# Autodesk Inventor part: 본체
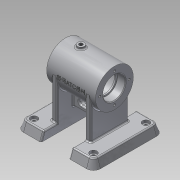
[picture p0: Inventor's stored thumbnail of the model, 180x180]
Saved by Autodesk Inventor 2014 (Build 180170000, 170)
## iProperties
Created: 2016-07
Part Number: 본체
Material: 알루미늄 6061
Document SubType Name: Modeling
Designer: net
Density: 2.71 g/cm^3
Appearance: 알루미늄 - 평지
Mass: 505.561 g
Surface Area: 530.336 cm^2
Volume: 186.554 cm^3
Author: net
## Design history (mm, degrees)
sketch "스케치1"
  geometry: C1 r 27 at (0, 0); 1 further point
  constraints: 1 centre point, 1 coincident
  dimensions: "d0" = 54 diameter of C1
extrude "돌출1" new body sketch "스케치1" stored distance "d1" = 70; taper "d2" = 0 deg
sketch "스케치2"
  geometry: C1 r 22 at (0, 0); 1 further point
  constraints: 1 centre point, 1 coincident
  dimensions: "d3" = 44 diameter of C1
extrude "돌출2" cut sketch "스케치2" stored distance "d4" = 42; taper "d5" = 0 deg
sketch "스케치3"
  geometry: C1 r 27 at (0, 0) reference; C2 r 14 at (0, 0)
  constraints: 1 centre point, 1 coincident
  dimensions: "d6" = 28 diameter of C2
extrude "돌출3" cut sketch "스케치3" stored distance "d7" = 42; taper "d8" = 0 deg
sketch "스케치4"
  geometry: C1 r 14 at (0, 0) reference; C2 r 27 at (0, 0) reference; C3 r 16 at (0, 0)
  constraints: 1 centre point, 1 coincident
  dimensions: "d9" = 32 diameter of C3
extrude "돌출4" cut sketch "스케치4" distance "d10" = 12; taper "d11" = 0 deg
sketch "스케치5"
  geometry: C1 r 14 at (0, 0) reference; C2 r 27 at (0, 0) reference; C3 r 16 at (0, 0)
  constraints: 1 centre point, 1 coincident
  dimensions: "d12" = 32 diameter of C3
extrude "돌출5" cut sketch "스케치5" distance "d13" = 12; taper "d14" = 0 deg
node "작업 평면1"
sketch "스케치6"
  geometry: L1 (-35, 27)-(-35, -27) reference; L2 (35, -27)-(35, 27) reference; L3 (-35, 0)-(35, 0); C1 r 5 at (-13, 0); 1 further point
  constraints: 2 end point, 2 midpoint, 1 centre point, 1 point on line
  dimensions: "d16" = 10 diameter of C1; "d17" = 22 distance of L3.start C1.centre
extrude "돌출6" join sketch "스케치6" stored distance "d18" = 12; taper "d19" = 0 deg
node "작업 평면3"
  node "작업 평면2"
sketch "스케치7"
  geometry: C1 r 6 at (0, 0); 1 further point
  constraints: 1 centre point, 1 coincident
  dimensions: "d22" = 12 diameter of C1
extrude "돌출7" join sketch "스케치7" stored distance "d23" = 10; taper "d24" = 0 deg
node "작업 평면4"
sketch "스케치9"
  geometry: L1 (-55, 50)-(-20, 50); L2 (-20, -50)-(-55, -50); L3 (-55, -50)-(-55, 50); L4 (0, 29.989)-(0, -29.989); L5 (55, 50)-(20, 50); L6 (55, -50)-(55, 50); L7 (20, -50)-(55, -50); L8 (-20, 50)-(20, 50); L9 (-20, -50)-(20, -50); C1 r 3 at (-42.5, 37.5); C2 r 3 at (-42.5, -37.5); C3 r 3 at (42.5, 37.5); C4 r 3 at (42.5, -37.5); 3 further points
  constraints: 18 end point, 6 symmetric about line, 4 centre point, 3 parallel, 2 midpoint, 1 coincident, 1 collinear, 1 horizontal, 1 horizontal alignment, 2 other
  dimensions: "d26" = 55 distance between parallel lines of L4 L3; "d27" = 100 distance of L2.end L1.start; "d28" = 35 distance of L1.start L1.end; "d29" = 6 diameter of C1; "d30" = 6 diameter of C2; "d31" = 12.5 distance from line of L2 C2.centre; "d32" = 12.5 distance from line of L3 C2.centre; "d33" = 12.5 distance from line of L1 C1.centre; "d34" = 12.5 distance from line of L3 C1.centre
extrude "돌출9" join sketch "스케치9" distance "d37" = 12; taper "d38" = -20 deg
sketch "스케치12"
  geometry: L1 (-23, 16)-(-35, 16) reference; L2 (-35, 16)-(-35, 27) reference; L3 (-35, 27)-(8, 27) reference; L4 (8, 27)-(8, 30) reference; L5 (8, 30)-(18, 30) reference; L6 (18, 30)-(18, 27) reference; L7 (18, 27)-(35, 27) reference; L8 (35, 27)-(35, 16) reference; L9 (35, 16)-(23, 16) reference; L10 (23, 16)-(23, 14) reference; L11 (23, 14)-(21, 14) reference; L12 (21, 14)-(21, 22) reference; L13 (21, 22)-(-21, 22) reference; L14 (-21, 22)-(-21, 14) reference; L15 (-21, 14)-(-23, 14) reference; L16 (-23, 14)-(-23, 16) reference; L17 (-35, -16)-(-23, -16) reference; L18 (-23, -16)-(-23, -14) reference; L19 (-23, -14)-(-21, -14) reference; L20 (-21, -14)-(-21, -22) reference; L21 (-21, -22)-(21, -22) reference; L22 (21, -22)-(21, -14) reference; L23 (21, -14)-(23, -14) reference; L24 (23, -14)-(23, -16) reference; L25 (23, -16)-(35, -16) reference; L26 (35, -16)-(35, -27) reference; L27 (35, -27)-(-35, -27) reference; L28 (-35, -27)-(-35, -16) reference; L29 (50.632, -58)-(55, -70) reference; L30 (55, -70)-(-55, -70) reference; L31 (-55, -70)-(-50.632, -58) reference; L32 (-50.632, -58)-(50.632, -58) reference; L33 (0, -70)-(0, 22); L34 (-20, -70)-(20, -70); L35 (20, -70)-(20, -58); L36 (20, -58)-(-20, -58); L37 (-20, -58)-(-20, -70); 1 further point
  constraints: 10 end point, 2 midpoint, 2 parallel, 2 point on line, 1 horizontal, 1 perpendicular
  dimensions: "d39" = 40 distance between parallel lines of L35 L37; "d40" = 20 distance between parallel lines of L33 L37
extrude "돌출10" cut sketch "스케치12" stored distance "d41" = 12; taper "d42" = 0 deg
sketch "스케치13"
  geometry: L1 (20, 50)-(20, -50) reference; L2 (-20, -50)-(-20, 50) reference; L3 (-20, 50)-(-55, 50) reference; L4 (-55, 50)-(-55, -50) reference; L5 (-55, -50)-(-20, -50) reference; L6 (-20, 50)-(20, 50); L7 (0, 50)-(0, -50); L8 (-20, 27)-(-28, 27); L9 (-28, 27)-(-28, -27); L10 (-28, -27)-(-20, -27); L11 (-20, -27)-(-20, 27); L12 (28, -27)-(20, -27); L13 (20, -27)-(20, 27); L14 (20, 27)-(28, 27); L15 (28, 27)-(28, -27); C1 r 3 at (-42.5, -37.5) reference; C2 r 3 at (-42.5, 37.5) reference; 1 further point
  constraints: 20 end point, 4 symmetric about line, 3 perpendicular, 2 parallel, 1 horizontal, 1 midpoint, 1 point on line
  dimensions: "d43" = 54 distance of L10.end L8.start; "d44" = 27 distance from line of point (0, 0) L8 (= 0.5 x d43); "d45" = 8 distance of L8.start L8.end
extrude "돌출11" join sketch "스케치13" stored distance "d46" = 12; taper "d47" = 0 deg
sketch "스케치14"
  geometry: L1 (23, -16)-(35, -16) reference; L2 (35, -16)-(35, -27) reference; L3 (35, -27)-(28, -27) reference; L4 (28, -27)-(28, -58) reference; L5 (28, -58)-(50.632, -58) reference; L6 (50.632, -58)-(55, -70) reference; L7 (55, -70)-(20, -70) reference; L8 (20, -70)-(20, -27) reference; L9 (20, -27)-(-20, -27) reference; L10 (-20, -27)-(-20, -70) reference; L11 (-20, -70)-(-55, -70) reference; L12 (-55, -70)-(-50.632, -58) reference; L13 (-50.632, -58)-(-28, -58) reference; L14 (-28, -58)-(-28, -27) reference; L15 (-28, -27)-(-35, -27) reference; L16 (-35, -27)-(-35, -16) reference; L17 (-35, -16)-(-23, -16) reference; L18 (-23, -16)-(-23, -14) reference; L19 (-23, -14)-(-21, -14) reference; L20 (-21, -14)-(-21, -22) reference; L21 (-21, -22)-(21, -22) reference; L22 (21, -22)-(21, -14) reference; L23 (21, -14)-(23, -14) reference; L24 (23, -14)-(23, -16) reference; L25 (35, 16)-(23, 16) reference; L26 (23, 16)-(23, 14) reference; L27 (23, 14)-(21, 14) reference; L28 (21, 14)-(21, 22) reference; L29 (21, 22)-(-21, 22) reference; L30 (-21, 22)-(-21, 14) reference; L31 (-21, 14)-(-23, 14) reference; L32 (-23, 14)-(-23, 16) reference; L33 (-23, 16)-(-35, 16) reference; L34 (-35, 16)-(-35, 27) reference; L35 (-35, 27)-(8, 27) reference; L36 (8, 27)-(8, 30) reference; L37 (8, 30)-(18, 30) reference; L38 (18, 30)-(18, 27) reference; L39 (18, 27)-(35, 27) reference; L40 (35, 27)-(35, 16) reference; L41 (-20, -48)-(20, -48); 1 further point
  constraints: 2 end point, 2 point on line, 1 perpendicular
  dimensions: "d48" = 21 distance between parallel lines of L15 L41
feature "리브1" sketch "스케치14" dims "d49" = 1, "d50" = 8, "d51" = 0, "d52" = 0, "d53" = 1, "d54" = 1
sketch "스케치15"
  geometry: L1 (10, 53.404)-(55, 53.404) reference; L2 (55, 53.404)-(55, 42.194) reference; L3 (55, 42.194)-(43, 42.194) reference; L4 (43, 42.194)-(43, 40.118) reference; L5 (43, 40.118)-(41, 40.118) reference; L6 (41, 40.118)-(41, 48.335) reference; L7 (41, 48.335)-(-1, 48.335) reference; L8 (-1, 48.335)-(-1, 40.118) reference; L9 (-1, 40.118)-(-3, 40.118) reference; L10 (-3, 40.118)-(-3, 42.194) reference; L11 (-3, 42.194)-(-15, 42.194) reference; L12 (-15, 42.194)-(-15, 53.404) reference; L13 (-15, 53.404)-(4, 53.404) reference; L14 (4, 53.404)-(4, 56.702) reference; L15 (4, 56.702)-(10, 56.702) reference; L16 (10, 56.702)-(10, 53.404) reference; L17 (0, -43.298)-(-35, -43.298) reference; L18 (-35, -43.298)-(-30.632, -31.298) reference; L19 (-30.632, -31.298)-(-8, -31.298) reference; L20 (-8, -31.298)-(-8, 0) reference; L21 (-8, 0)-(-15, 0) reference; L22 (-15, 0)-(-15, 11.21) reference; L23 (-15, 11.21)-(-3, 11.21) reference; L24 (-3, 11.21)-(-3, 13.286) reference; L25 (-3, 13.286)-(-1, 13.286) reference; L26 (-1, 13.286)-(-1, 5.069) reference; L27 (-1, 5.069)-(41, 5.069) reference; L28 (41, 5.069)-(41, 13.286) reference; L29 (41, 13.286)-(43, 13.286) reference; L30 (43, 13.286)-(43, 11.21) reference; L31 (43, 11.21)-(55, 11.21) reference; L32 (55, 11.21)-(55, 0) reference; L33 (55, 0)-(48, 0) reference; L34 (48, 0)-(48, -31.298) reference; L35 (48, -31.298)-(70.632, -31.298) reference; L36 (70.632, -31.298)-(75, -43.298) reference; L37 (75, -43.298)-(40, -43.298) reference; L38 (40, -43.298)-(40, -21.298) reference; L39 (40, -21.298)-(0, -21.298) reference; L40 (0, 0)-(0, -21.298) reference; L41 (40, 0)-(0, 0) reference; L42 (40, -21.298)-(40, 0) reference; L43 (0, -21.298)-(0, -43.298) reference; L44 (8.5, -11.298)-(31.5, -11.298); L45 (20, -21.298)-(20, 48.335); L46 (12, -7.798)-(28, -7.798); L47 (12, -14.798)-(28, -14.798); A1 r 3.5 centre (12, -11.298) between (12, -7.798) and (12, -14.798); A2 r 3.5 centre (28, -11.298) between (28, -14.798) and (28, -7.798); 2 further points
  constraints: 8 end point, 6 point on circle, 4 tangent, 3 midpoint, 3 point on line, 2 centre point, 1 equal radius, 1 perpendicular
  dimensions: "d55" = 32 distance between parallel lines of L37 L44; "d56" = 23 distance of L44.start L44.end; "d57" = 7 diameter of A1; "d58" = 11.5 distance of point (20, -11.298) L44.start (derived)
extrude "돌출12" cut sketch "스케치15" stored distance "d59" = 0; taper "d60" = 0 deg
node "작업 평면5"
sketch "스케치16"
  geometry: L1 (-35, 27)-(-35, -27) reference; L2 (35, -27)-(35, 27) reference; L3 (-35, 27)-(35, 27) reference; L4 (-35, -27)-(35, -27) reference; L5 (0, 27)-(0, -27); L6 (-35, 0)-(35, 0); L7 (-20.065, 7.274)-(20.065, 7.274); L8 (20.065, 7.274)-(20.065, -7.274); L9 (20.065, -7.274)-(-20.065, -7.274); L10 (-20.065, -7.274)-(-20.065, 7.274); L11 (-20.065, 0)-(20.065, 0); L12 (0, 7.274)-(0, -7.274); 1 further point
  constraints: 8 end point, 8 midpoint, 2 collinear, 2 other
  dimensions: "d62" = 35 distance between parallel lines of L1 L5 (derived); "d63" = 27 distance between parallel lines of L3 L6 (derived)
feature "엠보싱1" sketch "스케치16" dims "d64" = 0.5, "d65" = 0
sketch "스케치19"
  geometry: L1 (20, 50)-(20, -50) reference; L2 (20, 50)-(55, 50); L3 (55, 50)-(55, -50); L4 (55, -50)-(20, -50); L5 (20, -27)-(28, -27) reference; L6 (28, -27)-(28, 27) reference; L7 (28, 27)-(20, 27) reference; L8 (20, -27)-(28, -27); L9 (28, 27)-(28, -27); L10 (28, 27)-(20, 27); L11 (20, -50)-(20, -27); L12 (20, 27)-(20, 50); L13 (-55, -50)-(-20, -50) reference; L14 (0, 0)-(0, -58.48); L15 (-55, 50)-(-55, -50); L16 (-55, -50)-(-20, -50); L17 (-28, -27)-(-28, 27); L18 (-28, 27)-(-28, -27); L19 (-20, -27)-(-28, -27); L20 (-20, -27)-(-28, -27); L21 (-20, -50)-(-20, -27); L22 (-28, 27)-(-20, 27); L23 (-20, 27)-(-20, 50); L24 (-20, 50)-(-55, 50); L25 (-28, 27)-(-20, 27); C1 r 3 at (42.5, 37.5) reference; C2 r 3 at (42.5, -37.5) reference; 3 further points
  constraints: 40 end point, 8 symmetric about line, 3 parallel, 3 perpendicular, 2 collinear, 1 horizontal
extrude "돌출15" cut sketch "스케치19" distance "d71" = 12; taper "d72" = 0 deg
sketch "스케치20"
  geometry: L1 (-28, -27)-(-20, -27) reference; L2 (-20, -27)-(-20, 27) reference; L3 (-20, 27)-(-28, 27) reference; L4 (-28, 27)-(-28, -27) reference; L5 (-20, 50)-(-45, 50); L6 (-55, 40)-(-55, -40); L7 (-45, -50)-(-20, -50); L8 (-20, -50)-(-20, 50); L9 (0, 0)-(0, -50); L10 (20, 50)-(45, 50); L11 (55, 40)-(55, -40); L12 (45, -50)-(20, -50); L13 (20, -50)-(20, 50); A1 r 10 centre (-45, 40) between (-45, 50) and (-55, 40); A2 r 10 centre (-45, -40) between (-55, -40) and (-45, -50); A3 r 10 centre (45, 40) between (55, 40) and (45, 50); A4 r 10 centre (45, -40) between (45, -50) and (55, -40); 4 further points
  constraints: 18 end point, 10 symmetric about line, 8 point on circle, 8 point on line, 4 centre point, 4 tangent, 3 parallel, 1 collinear, 1 equal radius, 1 horizontal, 1 perpendicular, 2 other
  dimensions: "d73" = 100 distance of point (-55, 50) point (-55, -50); "d74" = 35 distance of L5.start point (-55, 50); "d75" = 50 distance from line of L9.start L5 (= 0.5 x d73); "d76" = 10 radius of A1
node "작업 평면6"
sketch "스케치22" dims "d81" = 42
  geometry: L1 (0, 0)-(21, 0); C1 r 27 at (0, 0) reference
  constraints: 2 end point, 1 coincident, 1 horizontal, 1 horizontal alignment, 2 other
sketch "스케치23" dims "d82" = 42
  geometry: L1 (-21, 0)-(0, 0); C1 r 16 at (0, 0) reference
  constraints: 2 end point, 1 coincident, 1 horizontal, 1 horizontal alignment, 2 other
hole "구멍1" sketch "스케치23" at (-21, 0) diameter "d83" = 3.242; stored, may be unused: countersink angle "d87" = 90 deg, drill point angle "d89" = 118 deg; dims "d84" = 8, "d85" = 4, "d86" = 2, "d88" = 10
hole "구멍2" sketch "스케치22" diameter "d90" = 3.242; stored, may be unused: countersink angle "d94" = 90 deg, drill point angle "d96" = 118 deg; dims "d91" = 8, "d92" = 4, "d93" = 2, "d95" = 10
sketch "스케치24"
  geometry: C1 r 5 at (0, 0) reference; 1 further point
sketch "스케치25"
  geometry: C1 r 6 at (0, 0) reference
hole "구멍3" sketch "스케치24" diameter "d100" = 5.188; stored, may be unused: countersink angle "d104" = 90 deg, drill point angle "d106" = 118 deg; dims "d101" = 48, "d102" = 4, "d103" = 2, "d105" = 10
hole "구멍4" sketch "스케치25" diameter "d107" = 5.188; stored, may be unused: countersink angle "d111" = 90 deg, drill point angle "d113" = 118 deg; dims "d108" = 35, "d109" = 4, "d110" = 2, "d112" = 10
fillet "모깎기1" dims "d114" = 3, "d115" = 0.3
chamfer "모따기1" distance "d116" = 1; stored, may be unused: second distance "d117" = 2, angle "d118" = 45 deg
fillet "모깎기2" dims "d119" = 2
extrude "돌출17" join sketch "스케치20" distance "d120" = 12; taper "d121" = 0 deg
feature "면 기울기2" dims angle "d122" = 20 deg
feature "면 기울기3" dims angle "d123" = -20 deg
fillet "모깎기3" dims "d124" = 2
fillet "모깎기4" dims "d125" = 2
fillet "모깎기5" dims "d126" = 2
fillet "모깎기6" dims "d127" = 2
fillet "모깎기7" dims "d128" = 2
sketch "스케치27"
  geometry: L1 (-20, -47.872)-(-20, 47.872) reference; L2 (-45, -50)-(-22, -50) reference; L3 (-55, 40)-(-55, -40) reference; L4 (-22, 50)-(-45, 50) reference; L5 (22, 50)-(45, 50) reference; L6 (55, 40)-(55, -40) reference; L7 (45, -50)-(22, -50) reference; L8 (20, -47.872)-(20, 47.872) reference; L9 (-55, 0)-(55, 0); L10 (-22, 50)-(22, 50); L11 (-22, -50)-(22, -50); L12 (0, 0)-(0, -50); C1 r 5 at (-42.5, -37.5); C2 r 5 at (-42.5, 37.5); C3 r 5 at (42.5, -37.5); C4 r 5 at (42.5, 37.5); A1 r 10 centre (-45, -40) between (-55, -40) and (-45, -50) reference; A2 r 10 centre (-45, 40) between (-45, 50) and (-55, 40) reference; A3 r 10 centre (45, 40) between (55, 40) and (45, 50) reference; A4 r 10 centre (45, -40) between (45, -50) and (55, -40) reference; 4 further points; 4 other entities
  constraints: 8 end point, 4 centre point, 4 horizontal, 4 midpoint, 3 symmetric about line, 1 collinear, 1 parallel, 7 other
  dimensions: "d129" = 12.5 distance from line of L3 C1.centre; "d130" = 12.5 distance from line of L2 C1.centre; "d131" = 10 diameter of C1
extrude "돌출18" cut sketch "스케치27" distance "d132" = 4; taper "d133" = 0 deg
sketch "스케치28"
  geometry: L1 (22.5, -10.372)-(22.5, 85.372) reference; L2 (-2.5, -12.5)-(20.5, -12.5) reference; L3 (-12.5, 77.5)-(-12.5, -2.5) reference; L4 (20.5, 87.5)-(-2.5, 87.5) reference; L5 (64.5, 87.5)-(87.5, 87.5) reference; L6 (97.5, 77.5)-(97.5, -2.5) reference; L7 (87.5, -12.5)-(64.5, -12.5) reference; L8 (62.5, -10.372)-(62.5, 85.372) reference; L9 (42.5, 37.5)-(22.5, 37.5); L10 (20.5, 87.5)-(64.5, 87.5); L11 (42.5, 87.5)-(42.5, 37.5); C1 r 5 at (0, 0) reference; C2 r 3 at (0, 0); C3 r 3 at (85, 0); C4 r 3 at (0, 75); C5 r 3 at (85, 75); A1 r 10 centre (-2.5, -2.5) between (-12.5, -2.5) and (-2.5, -12.5) reference; A2 r 10 centre (-2.5, 77.5) between (-2.5, 87.5) and (-12.5, 77.5) reference; A3 r 10 centre (87.5, 77.5) between (97.5, 77.5) and (87.5, 87.5) reference; A4 r 10 centre (87.5, -2.5) between (87.5, -12.5) and (97.5, -2.5) reference; 4 further points; 4 other entities
  constraints: 6 end point, 4 centre point, 3 symmetric about line, 2 horizontal, 2 midpoint, 1 coincident, 1 parallel, 1 perpendicular, 7 other
  dimensions: "d134" = 6 diameter of C2
extrude "돌출19" cut sketch "스케치28" stored distance "d135" = 4; taper "d136" = 0 deg
node "솔리드1"
pattern_circular "원형 패턴1" dims angle "d98" = 360 deg
node "투영된 루프1"
node "투영된 루프5"
node "투영된 루프6"
node "투영된 루프7"
node "투영된 루프8"
node "절단 모서리 투영3"
node "절단 모서리 투영4"
node "절단 모서리 투영5"
other parameters: "d20" = 32 deg, "d61" = -55, "d80" = -12
